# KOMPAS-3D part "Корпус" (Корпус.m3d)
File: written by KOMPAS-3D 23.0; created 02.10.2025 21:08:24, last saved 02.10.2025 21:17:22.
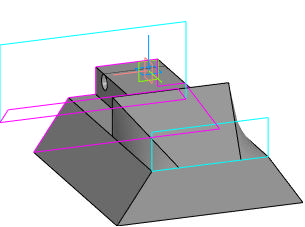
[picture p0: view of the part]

Document properties: Автор: Inspektor_Kot; Полное имя файла: I:\Autodesk Inventor Projects\ИМ-ИТ ЦД\Вариант 9\Корпус.m3d

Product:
- Part/product: Корпус
    Масса: 277.048386

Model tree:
1. Эскиз:1  (with: Элемент выдавливания:1)
2. Смещенная плоскость:1  (with: Элемент выдавливания:1)
     Расстояние = 270
3. Эскиз:2  (with: Элемент выдавливания:2)
4. Элемент по сечениям:1
5. Эскиз:3  (with: Элемент по сечениям:1, Элемент выдавливания:2, Элемент выдавливания:1)
6. Элемент выдавливания:1
     Расстояние 1 = 300
7. Эскиз:4  (with: Элемент выдавливания:1)
8. Смещенная плоскость:2  (with: Элемент выдавливания:1)
     Расстояние = 230
9. Эскиз:5  (with: Элемент выдавливания:1)
10. Эскиз:6  (with: Элемент выдавливания:1, Элемент выдавливания:3)
11. Элемент выдавливания:2
     Расстояние 2 = 320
